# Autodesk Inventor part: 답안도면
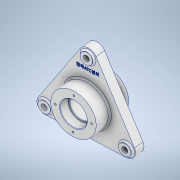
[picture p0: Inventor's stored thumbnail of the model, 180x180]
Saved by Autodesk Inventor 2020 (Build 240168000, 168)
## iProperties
Created: 2023-04
Part Number: 답안도면
Material: Aluminum 6061
Document SubType Name: Modeling
Designer: home
Density: 2.7 g/cm^3
Appearance: Aluminum - Flat
Mass: 1221.4 g
Surface Area: 646.868 cm^2
Volume: 452.371 cm^3
Author: home
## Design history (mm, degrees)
sketch "Sketch1" dims "d0" = 164
  geometry: L1 (-13.856, 90)-(-84.87, -33); L2 (13.856, 90)-(84.87, -33); L3 (-71.014, -57)-(71.014, -57); A1 r 16 centre (0, 82) between (-13.856, 90) and (13.856, 90); A2 r 16 centre (-71.014, -41) between (-71.014, -57) and (-84.87, -33); A3 r 16 centre (71.014, -41) between (84.87, -33) and (71.014, -57); 2 further points
  constraints: 6 end point, 6 point on circle, 5 tangent, 3 centre point, 2 vertical alignment, 1 coincident, 1 horizontal, 9 other
  dimensions: "d1" = 32 diameter of A1; "d4" = 360 deg dimension on point (0, 0) A1.centre (derived)
extrude "Extrusion1" new body sketch "Sketch1" stored distance "d6" = 18; taper "d7" = 0 deg
sketch "Sketch2"
  geometry: L1 (90, 9)-(-33, 9) reference; L2 (-33, -9)-(90, -9) reference; L3 (0, 32)-(0, -38); L4 (45, 9)-(45, 14); L5 (45, 14)-(40, 14); L6 (40, 14)-(40, 32); L7 (40, 32)-(0, 32); L8 (40, -4.592)-(40, -38); L9 (40, -38)-(0, -38); 4 further points
  constraints: 14 end point, 4 perpendicular, 3 vertical, 2 point on line
  dimensions: "d8" = 90 diameter of L4 L3; "d9" = 80 diameter of L6 L3; "d10" = 80 diameter of L8 L3; "d11" = 5 distance between parallel lines of L1 L5; "d12" = 23 distance between parallel lines of L7 L1; "d13" = 70 distance between parallel lines of L9 L7
revolve "Revolution1" sketch "Sketch2" stored, may be unused: angle "d14" = 90 deg
sketch "Sketch3"
  geometry: C1 r 23.5 at (0, 0); 1 further point
  constraints: 1 centre point, 1 coincident
  dimensions: "d15" = 47 diameter of C1
extrude "Extrusion2" cut sketch "Sketch3" distance "d16" = 17; taper "d17" = 0 deg
sketch "Sketch4"
  geometry: C1 r 23.5 at (0, 0); 1 further point
  constraints: 1 centre point, 1 coincident
  dimensions: "d18" = 47 diameter of C1
extrude "Extrusion3" cut sketch "Sketch4" distance "d19" = 17; taper "d20" = 0 deg
sketch "Sketch5"
  geometry: C1 r 21 at (0, 0); 1 further point
  constraints: 1 centre point, 1 coincident
  dimensions: "d21" = 42 diameter of C1
extrude "Extrusion4" cut sketch "Sketch5" extent not by distance; stored distance "d22" = 17; taper "d23" = 0 deg
sketch "Sketch6"
  geometry: 2 further points
  constraints: 1 vertical alignment
  dimensions: "d24" = 32 distance of point (0, 32) point (0, 0)
hole "Hole1" sketch "Sketch6" at (0, 32) diameter "d25" = 3.242; stored, may be unused: countersink angle "d29" = 90 deg, drill point angle "d31" = 118 deg; dims "d26" = 8, "d27" = 4, "d28" = 2, "d30" = 10
pattern_circular "Circular Pattern1" dims angle "d33" = 360 deg
sketch "Sketch7"
  geometry: 2 further points
  constraints: 1 vertical alignment
  dimensions: "d35" = 32 distance of point (0, 0) point (0, 32)
hole "Hole2" sketch "Sketch7" at (0, 32) diameter "d36" = 3.242; stored, may be unused: countersink angle "d40" = 90 deg, drill point angle "d42" = 118 deg; dims "d37" = 8, "d38" = 4, "d39" = 2, "d41" = 10
pattern_circular "Circular Pattern2" dims angle "d44" = 360 deg
sketch "Sketch8"
  geometry: C1 r 11 at (0, 82); A1 r 16 centre (0, 82) between (13.856, 90) and (-13.856, 90) reference; 1 further point
  constraints: 1 centre point, 1 concentric, 1 vertical alignment
  dimensions: "d46" = 22 diameter of C1
extrude "Extrusion5" join sketch "Sketch8" distance "d48" = 4; taper "d49" = 0 deg
sketch "Sketch9"
  geometry: C1 r 5.5 at (0, 0); C2 r 11 at (0, 0) reference; 2 further points
  constraints: 1 centre point, 1 coincident, 1 concentric
  dimensions: "d50" = 11 diameter of C1
extrude "Extrusion6" cut sketch "Sketch9" extent not by distance; stored distance "d51" = 0; taper "d52" = 0 deg
pattern_circular "Circular Pattern3" dims angle "d54" = 360 deg
fillet "Fillet1" dims "d56" = 3
chamfer "Chamfer1" distance "d57" = 1; stored, may be unused: second distance "d58" = 2, angle "d59" = 45 deg
sketch "Sketch10"
  geometry: L1 (-34.095, 64.049)-(34.095, 64.049); L2 (34.095, 64.049)-(34.095, 57.5); L3 (34.095, 57.5)-(-34.095, 57.5); L4 (-34.095, 57.5)-(-34.095, 64.049); 2 further points
  constraints: 1 midpoint, 1 vertical alignment, 2 other
  dimensions: "d60" = 57.5 distance from line of point (0, 0) L3
emboss "Emboss1" sketch "Sketch10" dims "d8" = 90, "d9" = 80, "d10" = 80, "d11" = 5, "d12" = 23, "d13" = 70, "d61" = 0.5, "d62" = 0
body "Solid1"
